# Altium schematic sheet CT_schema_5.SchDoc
size 297 x 173 mm
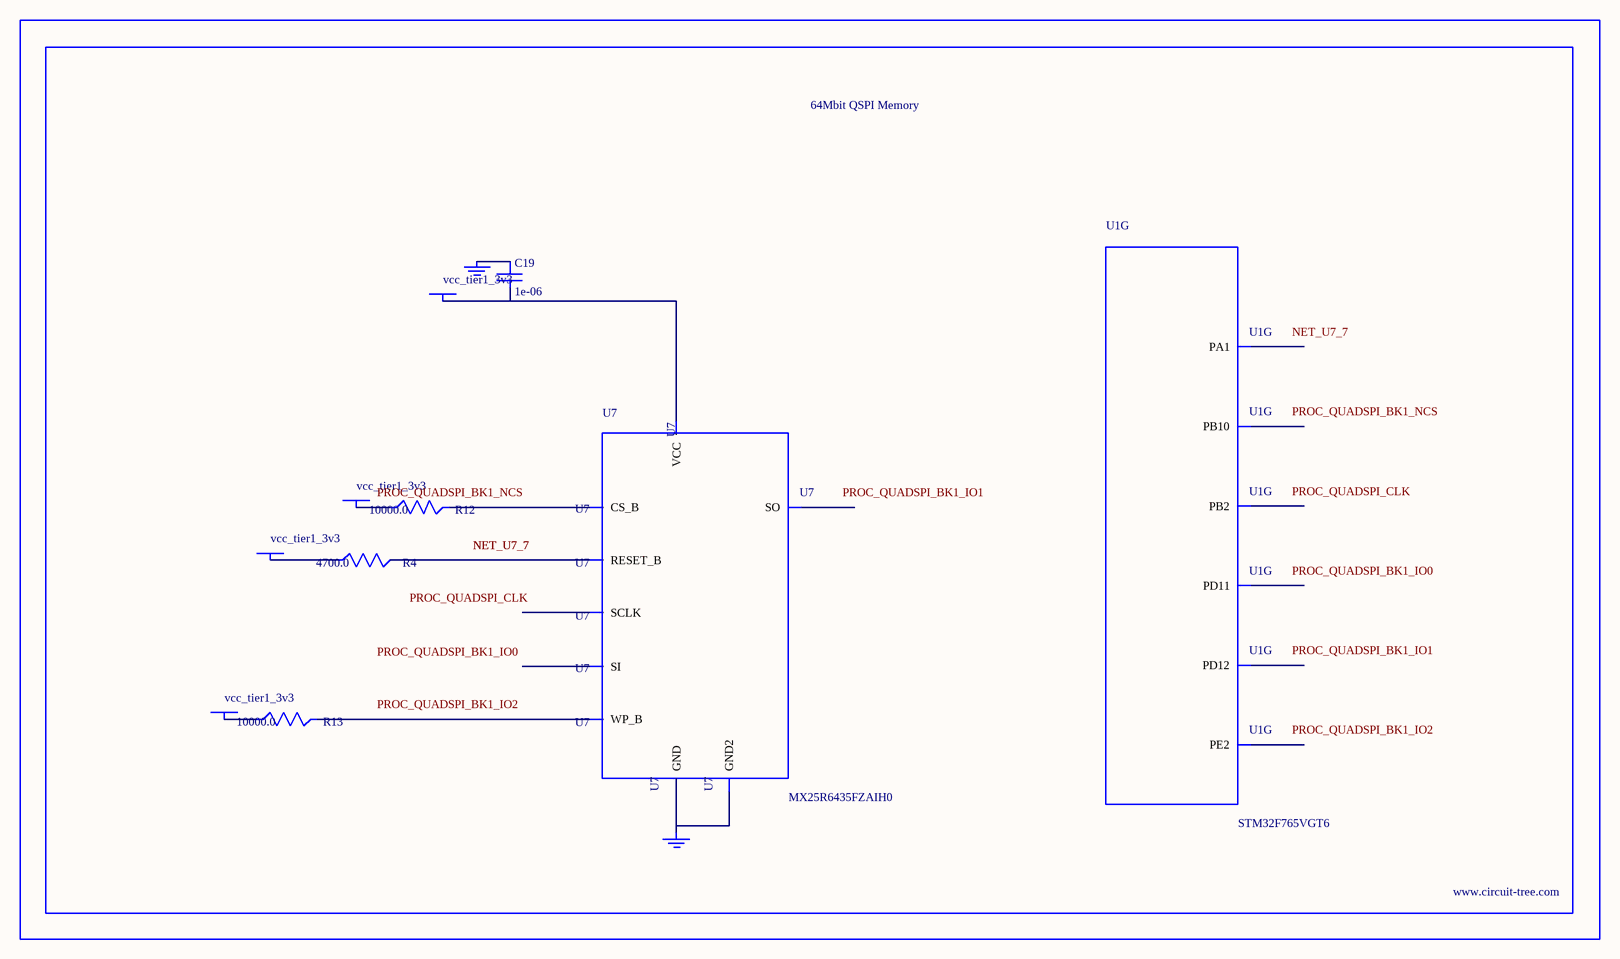
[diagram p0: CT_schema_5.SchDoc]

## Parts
BORDER4  (no value)
C19  1e-06  [C0603]
GND_INSTANCE_4_0  (no value)
GND_INSTANCE_4_1  (no value)
POWER_INSTANCE_4_0  vcc_tier1_3v3
POWER_INSTANCE_4_1  vcc_tier1_3v3
POWER_INSTANCE_4_2  vcc_tier1_3v3
POWER_INSTANCE_4_3  vcc_tier1_3v3
R4  4700.0  [R0603]
R12  10000.0  [R0603]
R13  10000.0  [R0603]
U1  STM32F765VGT6  [LQFP100]  (part G of 8)
U7  MX25R6435FZAIH0  [WSON-8-PAD]

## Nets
NetC19_1: C19.1 GND_INSTANCE_4_0.0(GND)
NetC19_2: C19.2 POWER_INSTANCE_4_2.0(PWR) U7.8(VCC)
NetGND_INSTANCE_4_1_0: GND_INSTANCE_4_1.0(GND) U7.4(GND) U7.PAD(GND2)
NetPOWER_INSTANCE_4_0_0: POWER_INSTANCE_4_0.0(PWR) R12.1
NetPOWER_INSTANCE_4_1_0: POWER_INSTANCE_4_1.0(PWR) R13.1
NetPOWER_INSTANCE_4_3_0: POWER_INSTANCE_4_3.0(PWR) R4.1
NetR4_2: R4.2 U7.7(RESET_B)
NetR12_2: R12.2 U7.1(CS_B)
NetR13_2: R13.2 U7.3(WP_B)

Not connected (* = marked no-connect by the designer): U1 1(PE2) 23(PA1) 36(PB2) 46(PB10) 58(PD11) 59(PD12); U7 2(SO) 5(SI) 6(SCLK)

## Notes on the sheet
- Labels drawn without touching a wire or pin: NET_U7_7, PROC_QUADSPI_BK1_IO0, PROC_QUADSPI_BK1_IO1, PROC_QUADSPI_BK1_IO2, PROC_QUADSPI_BK1_NCS, PROC_QUADSPI_CLK

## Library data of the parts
BORDER4 = BORDER_PAGE4
C19 = C0603C105K3RACTU
GND_INSTANCE_4_0 GND_INSTANCE_4_1 = GND
POWER_INSTANCE_4_0-POWER_INSTANCE_4_3 = PWR
R4 = RC0603JR-074K7L
R12 R13 = RC0603JR-0710KL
